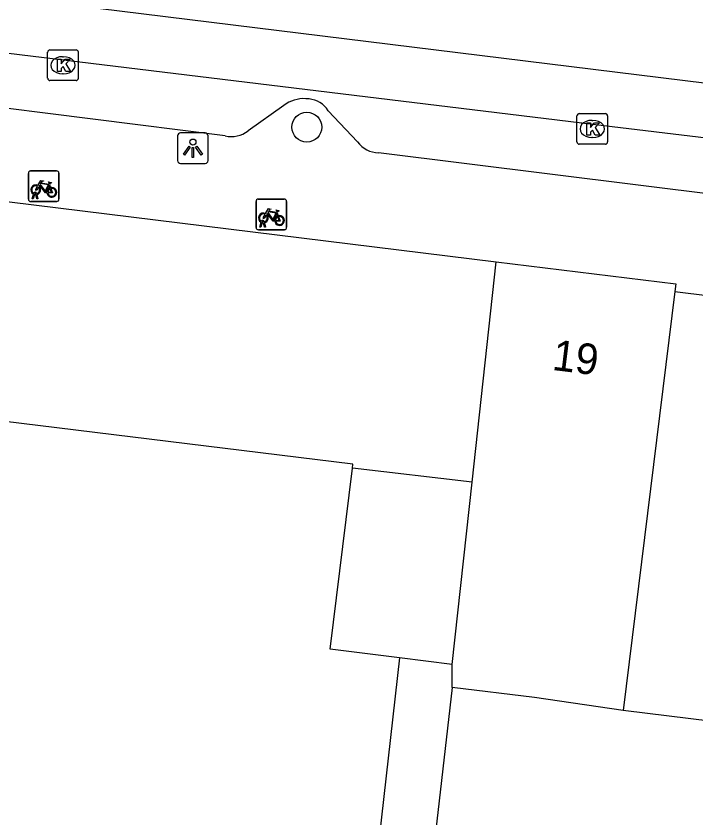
# Model space of a CAD drawing. Extents: x 161696 to 162377, y 380761 to 381673.
# Drawn here: x 162184.97 to 162207.17, y 381198.84 to 381225.02 of the extents above; entities that cross this region are included whole.
import ezdxf

# ---------------------------------------------------------------- set-up
doc = ezdxf.new("R2010")
doc.units = 0
for name, color, linetype in [('IMGEO_Boom', 7, 'Continuous'), ('IMGEO_Fietsenrek', 7, 'Continuous'), ('IMGEO_Kolk', 7, 'Continuous'), ('IMGEO_Lichtpunt', 7, 'Continuous'), ('IMGEO_Pand', 7, 'Continuous'), ('IMGEO_Pand_nummerreeks', 7, 'Continuous'), ('IMGEO_Rijbaan_lokaal_gesloten', 7, 'Continuous'), ('IMGEO_Voetpad_open', 7, 'Continuous')]:
    doc.layers.add(name, color=color, linetype=linetype)

msp = doc.modelspace()

# ---------------------------------------------------------------- linework, layer by layer
at = {"layer": 'IMGEO_Boom'}
msp.add_circle((162194.465, 381221.395), 0.489, dxfattribs=at)
at = {"layer": 'IMGEO_Fietsenrek'}
for p, q in [((162185.373, 381219.041), (162185.373, 381219.882)), ((162185.373, 381219.882), (162185.373, 381219.041)), ((162185.448, 381219.966), (162186.289, 381219.966)), ((162186.289, 381219.966), (162185.448, 381219.966)), ((162186.373, 381219.891), (162186.373, 381219.05)), ((162186.373, 381219.05), (162186.373, 381219.891)), ((162186.06, 381219.515), (162186.096, 381219.42)), ((162185.5, 381219.05), (162185.539, 381219.21)), ((162185.569, 381219.198), (162185.534, 381219.05)), ((162185.611, 381219.222), (162185.61, 381219.226)), ((162185.652, 381219.05), (162185.618, 381219.192)), ((162185.642, 381219.233), (162185.643, 381219.226)), ((162185.65, 381219.196), (162185.685, 381219.05)), ((162186.298, 381218.966), (162185.457, 381218.966)), ((162185.457, 381218.966), (162186.298, 381218.966)), ((162185.534, 381219.05), (162185.5, 381219.05)), ((162185.685, 381219.05), (162185.652, 381219.05)), ((162192.807, 381218.122), (162192.807, 381218.963)), ((162192.807, 381218.963), (162192.807, 381218.122)), ((162192.882, 381219.047), (162193.723, 381219.047)), ((162193.723, 381219.047), (162192.882, 381219.047)), ((162193.807, 381218.972), (162193.807, 381218.131)), ((162193.807, 381218.131), (162193.807, 381218.972)), ((162193.494, 381218.596), (162193.53, 381218.501)), ((162192.934, 381218.131), (162192.973, 381218.291)), ((162193.003, 381218.279), (162192.968, 381218.131)), ((162193.045, 381218.303), (162193.044, 381218.307)), ((162193.086, 381218.131), (162193.052, 381218.273)), ((162193.076, 381218.314), (162193.077, 381218.307)), ((162193.084, 381218.277), (162193.119, 381218.131)), ((162193.732, 381218.047), (162192.891, 381218.047)), ((162192.891, 381218.047), (162193.732, 381218.047)), ((162192.968, 381218.131), (162192.934, 381218.131)), ((162193.119, 381218.131), (162193.086, 381218.131))]:
    msp.add_line(p, q, dxfattribs=at)
for points in [[(162185.686, 381219.492), (162185.781, 381219.656), (162185.867, 381219.642), (162185.869, 381219.633), (162185.813, 381219.622), (162185.786, 381219.577), (162186.042, 381219.536)], [(162186.042, 381219.536), (162186.067, 381219.585), (162186.061, 381219.589), (162186.038, 381219.593), (162186.026, 381219.6), (162186.025, 381219.603), (162186.027, 381219.608), (162186.122, 381219.593), (162186.124, 381219.583), (162186.114, 381219.57), (162186.102, 381219.564), (162186.088, 381219.57), (162186.06, 381219.515)], [(162185.707, 381219.44), (162185.655, 381219.35), (162185.615, 381219.325), (162185.616, 381219.372), (162185.671, 381219.466)], [(162185.982, 381219.248), (162185.932, 381219.248), (162185.741, 381219.499), (162185.722, 381219.467)], [(162186.029, 381219.511), (162185.772, 381219.552), (162185.755, 381219.523), (162185.922, 381219.303), (162186.029, 381219.511)], [(162186.077, 381219.413), (162186.047, 381219.49), (162185.938, 381219.272), (162185.981, 381219.272)], [(162186.011, 381219.272), (162186.131, 381219.271), (162186.087, 381219.385)], [(162186.107, 381219.392), (162186.162, 381219.247), (162186.012, 381219.247)], [(162193.141, 381218.521), (162193.089, 381218.431), (162193.049, 381218.406), (162193.05, 381218.453), (162193.105, 381218.547)], [(162193.12, 381218.573), (162193.215, 381218.737), (162193.301, 381218.723), (162193.303, 381218.714), (162193.247, 381218.703), (162193.22, 381218.658), (162193.476, 381218.617)], [(162193.416, 381218.329), (162193.366, 381218.329), (162193.175, 381218.58), (162193.156, 381218.548)], [(162193.463, 381218.592), (162193.206, 381218.633), (162193.189, 381218.604), (162193.356, 381218.384), (162193.463, 381218.592)], [(162193.511, 381218.494), (162193.481, 381218.571), (162193.372, 381218.353), (162193.415, 381218.353)], [(162193.476, 381218.617), (162193.501, 381218.666), (162193.495, 381218.67), (162193.472, 381218.674), (162193.46, 381218.681), (162193.459, 381218.684), (162193.461, 381218.689), (162193.556, 381218.674), (162193.558, 381218.664), (162193.548, 381218.651), (162193.536, 381218.645), (162193.522, 381218.651), (162193.494, 381218.596)], [(162193.445, 381218.353), (162193.565, 381218.352), (162193.521, 381218.466)], [(162193.541, 381218.473), (162193.596, 381218.328), (162193.446, 381218.328)]]:
    msp.add_lwpolyline(points, dxfattribs=at)
for centre, radius, start, end in [((162185.451, 381219.888), 0.0779, 92.4484, 184.2845), ((162185.451, 381219.888), 0.0779, 92.4484, 184.2845), ((162186.295, 381219.888), 0.0779, 2.4484, 94.2845), ((162186.295, 381219.888), 0.0779, 2.4484, 94.2845), ((162185.613, 381219.351), 0.159, 62.6766, 242.1369), ((162185.613, 381219.351), 0.129, 63.3192, 238.903), ((162185.613, 381219.351), 0.129, 283.6043, 43.4302), ((162185.613, 381219.351), 0.159, 283.5766, 46.6042), ((162186.14, 381219.267), 0.159, 113.3408, 178.3217), ((162186.14, 381219.267), 0.159, 187.0065, 105.7708), ((162186.14, 381219.267), 0.129, 113.923, 177.9556), ((162186.14, 381219.267), 0.129, 188.6715, 104.5883), ((162185.593, 381219.222), 0.0499, 12.8025, 158.6934), ((162185.613, 381219.351), 0.159, 253.9967, 271.7867), ((162185.593, 381219.222), 0.0174, 12.8025, 163.4502), ((162185.613, 381219.351), 0.129, 253.415, 269.0204), ((162185.451, 381219.044), 0.0779, 182.4484, 274.2845), ((162185.451, 381219.044), 0.0779, 182.4484, 274.2845), ((162186.295, 381219.044), 0.0779, 272.4484, 4.2845), ((162186.295, 381219.044), 0.0779, 272.4484, 4.2845), ((162192.885, 381218.969), 0.0779, 92.4484, 184.2845), ((162192.885, 381218.969), 0.0779, 92.4484, 184.2845), ((162193.729, 381218.969), 0.0779, 2.4484, 94.2845), ((162193.729, 381218.969), 0.0779, 2.4484, 94.2845), ((162193.047, 381218.432), 0.159, 62.6766, 242.1369), ((162193.047, 381218.432), 0.129, 63.3192, 238.903), ((162193.047, 381218.432), 0.159, 283.5766, 46.6042), ((162193.027, 381218.303), 0.0499, 12.8025, 158.6934), ((162193.047, 381218.432), 0.159, 253.9967, 271.7867), ((162193.027, 381218.303), 0.0174, 12.8025, 163.4502), ((162193.047, 381218.432), 0.129, 253.415, 269.0204), ((162193.047, 381218.432), 0.129, 283.6043, 43.4302), ((162193.574, 381218.348), 0.159, 113.3408, 178.3217), ((162193.574, 381218.348), 0.159, 187.0065, 105.7708), ((162193.574, 381218.348), 0.129, 113.923, 177.9556), ((162193.574, 381218.348), 0.129, 188.6715, 104.5883), ((162192.885, 381218.125), 0.0779, 182.4484, 274.2845), ((162192.885, 381218.125), 0.0779, 182.4484, 274.2845), ((162193.729, 381218.125), 0.0779, 272.4484, 4.2845), ((162193.729, 381218.125), 0.0779, 272.4484, 4.2845)]:
    msp.add_arc(centre, radius, start, end, dxfattribs=at)
at = {"layer": 'IMGEO_Kolk'}
for p, q in [((162186.004, 381222.99), (162186.004, 381223.842)), ((162186.079, 381223.916), (162186.931, 381223.916)), ((162187.005, 381223.842), (162187.005, 381222.99)), ((162186.492, 381223.696), (162186.517, 381223.696)), ((162186.515, 381223.136), (162186.49, 381223.136)), ((162186.931, 381222.916), (162186.079, 381222.916)), ((162203.286, 381220.911), (162203.286, 381221.763)), ((162203.361, 381221.837), (162204.213, 381221.837)), ((162204.287, 381221.763), (162204.287, 381220.911)), ((162203.774, 381221.617), (162203.799, 381221.617)), ((162203.797, 381221.057), (162203.772, 381221.057)), ((162204.213, 381220.837), (162203.361, 381220.837))]:
    msp.add_line(p, q, dxfattribs=at)
for points in [[(162186.004, 381222.99), (162186.004, 381223.842)], [(162186.079, 381223.916), (162186.931, 381223.916)], [(162187.005, 381223.842), (162187.005, 381222.99)], [(162186.325, 381223.616), (162186.448, 381223.616), (162186.448, 381223.465), (162186.578, 381223.616), (162186.742, 381223.616), (162186.596, 381223.465), (162186.749, 381223.216), (162186.597, 381223.216), (162186.512, 381223.38), (162186.448, 381223.313), (162186.448, 381223.216), (162186.325, 381223.216), (162186.325, 381223.616)], [(162186.931, 381222.916), (162186.079, 381222.916)], [(162203.286, 381220.911), (162203.286, 381221.763)], [(162203.361, 381221.837), (162204.213, 381221.837)], [(162204.287, 381221.763), (162204.287, 381220.911)], [(162203.607, 381221.537), (162203.73, 381221.537), (162203.73, 381221.386), (162203.86, 381221.537), (162204.024, 381221.537), (162203.878, 381221.386), (162204.031, 381221.137), (162203.879, 381221.137), (162203.794, 381221.301), (162203.73, 381221.234), (162203.73, 381221.137), (162203.607, 381221.137), (162203.607, 381221.537)], [(162204.213, 381220.837), (162203.361, 381220.837)]]:
    msp.add_lwpolyline(points, dxfattribs=at)
for centre, start, end in [((162186.081, 381223.84), 91.552, 178.448), ((162186.081, 381223.84), 91.552, 178.448), ((162186.929, 381223.84), 1.552, 88.448), ((162186.929, 381223.84), 1.552, 88.448), ((162186.081, 381222.992), 181.552, 268.448), ((162186.081, 381222.992), 181.552, 268.448), ((162186.929, 381222.992), 271.552, 358.448), ((162186.929, 381222.992), 271.552, 358.448), ((162203.363, 381221.761), 91.552, 178.448), ((162203.363, 381221.761), 91.552, 178.448), ((162204.211, 381221.761), 1.552, 88.448), ((162204.211, 381221.761), 1.552, 88.448), ((162203.363, 381220.913), 181.552, 268.448), ((162203.363, 381220.913), 181.552, 268.448), ((162204.211, 381220.913), 271.552, 358.448), ((162204.211, 381220.913), 271.552, 358.448)]:
    msp.add_arc(centre, 0.0765, start, end, dxfattribs=at)
for centre, major_axis, ratio, start_param, end_param in [((162186.491, 381223.416), (-0.387, 0.002), 0.722429, 4.712389, 7.853982), ((162186.516, 381223.416), (-0.39, 0.002), 0.717154, 1.570796, 4.712389), ((162203.773, 381221.337), (-0.387, 0.002), 0.722429, 4.712389, 7.853982), ((162203.798, 381221.337), (-0.39, 0.002), 0.717154, 1.570796, 4.712389)]:
    msp.add_ellipse(centre, major_axis=major_axis, ratio=ratio, start_param=start_param, end_param=end_param, dxfattribs=at)
at = {"layer": 'IMGEO_Lichtpunt'}
for p, q in [((162191.149, 381221.205), (162190.341, 381221.205)), ((162191.149, 381221.205), (162190.341, 381221.205)), ((162190.247, 381221.11), (162190.247, 381220.303)), ((162190.247, 381221.11), (162190.247, 381220.303)), ((162191.243, 381220.303), (162191.243, 381221.11)), ((162191.243, 381220.303), (162191.243, 381221.11)), ((162190.341, 381220.209), (162191.149, 381220.209)), ((162190.341, 381220.209), (162191.149, 381220.209))]:
    msp.add_line(p, q, dxfattribs=at)
for points in [[(162190.621, 381220.774), (162190.66, 381220.746), (162190.472, 381220.484), (162190.434, 381220.511), (162190.621, 381220.774)], [(162190.723, 381220.726), (162190.77, 381220.726), (162190.77, 381220.404), (162190.723, 381220.404), (162190.723, 381220.726)], [(162190.833, 381220.746), (162190.871, 381220.773), (162191.058, 381220.511), (162191.019, 381220.483), (162190.833, 381220.746)]]:
    msp.add_lwpolyline(points, dxfattribs=at)
msp.add_circle((162190.746, 381220.908), 0.0994, dxfattribs=at)
for centre, start, end in [((162190.341, 381221.11), 90, 180), ((162190.341, 381221.11), 90, 180), ((162191.149, 381221.11), 0, 90), ((162191.149, 381221.11), 0, 90), ((162190.341, 381220.303), 180, 270), ((162190.341, 381220.303), 180, 270), ((162191.149, 381220.303), 270, 0), ((162191.149, 381220.303), 270, 360)]:
    msp.add_arc(centre, 0.0946, start, end, dxfattribs=at)
at = {"layer": 'IMGEO_Pand'}
for points in [[(162175.215, 381220.135), (162200.644, 381217)], [(162199.862, 381209.809), (162200.644, 381217)], [(162200.644, 381217), (162206.516, 381216.276), (162206.486, 381216.027)], [(162206.486, 381216.027), (162204.798, 381202.356)], [(162206.486, 381216.027), (162212.19, 381215.324)], [(162195.955, 381210.26), (162195.971, 381210.391), (162184.525, 381211.801), (162184.5, 381211.582)], [(162197.492, 381204.07), (162195.227, 381204.349), (162195.955, 381210.26)], [(162199.862, 381209.809), (162195.955, 381210.26)], [(162199.215, 381203.858), (162199.862, 381209.809)], [(162199.215, 381203.858), (162197.492, 381204.07)], [(162199.213, 381203.105), (162199.215, 381203.858)], [(162204.798, 381202.356), (162201.896, 381202.774), (162199.213, 381203.105)], [(162210.572, 381201.645), (162207.712, 381201.997), (162204.798, 381202.356)]]:
    msp.add_lwpolyline(points, dxfattribs=at)
at = {"layer": 'IMGEO_Rijbaan_lokaal_gesloten'}
for points in [[(162181.003, 381226.106), (162206.021, 381223.02), (162219.985, 381221.297), (162235.933, 381219.33), (162285.948, 381213.063)], [(162180.773, 381224.291), (162203.806, 381221.498), (162214.838, 381220.161)]]:
    msp.add_lwpolyline(points, dxfattribs=at)
at = {"layer": 'IMGEO_Voetpad_open'}
for points in [[(162191.797, 381221.107), (162183.146, 381222.196)], [(162194.54, 381222.318), (162194.432, 381222.325)], [(162193.716, 381222.107), (162192.549, 381221.275)], [(162196.124, 381220.915), (162195.166, 381221.933)], [(162213.677, 381218.461), (162196.806, 381220.559)], [(162197.492, 381204.07), (162194.906, 381181.141), (162192.874, 381180.248), (162184.063, 381181.267)], [(162199.213, 381203.105), (162194.213, 381159.563), (162190.787, 381159.956), (162187.187, 381153.72), (162186.438, 381154.204)]]:
    msp.add_lwpolyline(points, dxfattribs=at)
for centre, radius, start, end in [((162194.373, 381221.232), 1.094, 86.9335, 126.9343), ((162194.444, 381221.461), 0.862, 33.1846, 83.6311), ((162191.994, 381221.99), 0.905, 257.403, 307.7836), ((162196.825, 381221.426), 0.867, 216.1045, 268.7669)]:
    msp.add_arc(centre, radius, start, end, dxfattribs=at)

# ---------------------------------------------------------------- texts
at = {"layer": 'IMGEO_Pand_nummerreeks'}
msp.add_text('19', height=1, rotation=352.9711, dxfattribs=at).set_placement((162202.448, 381213.473))

doc.saveas('drawing.dxf')
